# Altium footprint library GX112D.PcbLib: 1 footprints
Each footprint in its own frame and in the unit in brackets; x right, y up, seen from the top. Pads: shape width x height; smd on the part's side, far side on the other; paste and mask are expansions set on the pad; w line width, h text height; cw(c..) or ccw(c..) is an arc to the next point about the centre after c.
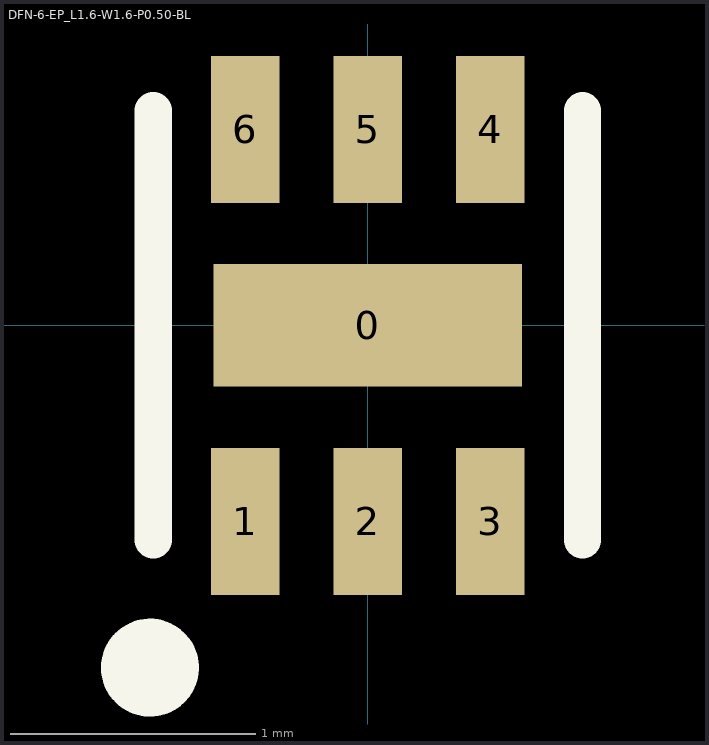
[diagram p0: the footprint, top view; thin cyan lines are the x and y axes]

## DFN-6-EP_L1.6-W1.6-P0.50-BL [mm]
pads (7):
  rect 1.26x0.5 smd: 0(0,0)
  rect 0.28x0.6 smd: 1(-0.5,-0.8) 2(0,-0.8) 3(0.5,-0.8) 4(0.5,0.8) 5(0,0.8) 6(-0.5,0.8)
Top Overlay:
  circle w0.2: c-0.889,-1.397 r0.1
  lines w0.152: -0.876,-0.876 -0.876,0.876 ; 0.876,-0.876 0.876,0.876
3D body "DFN-6-1.6X1.6-P0.5.STEP": height 0.61, standoff 0, extent -0.807,-0.835 0.813,0.785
